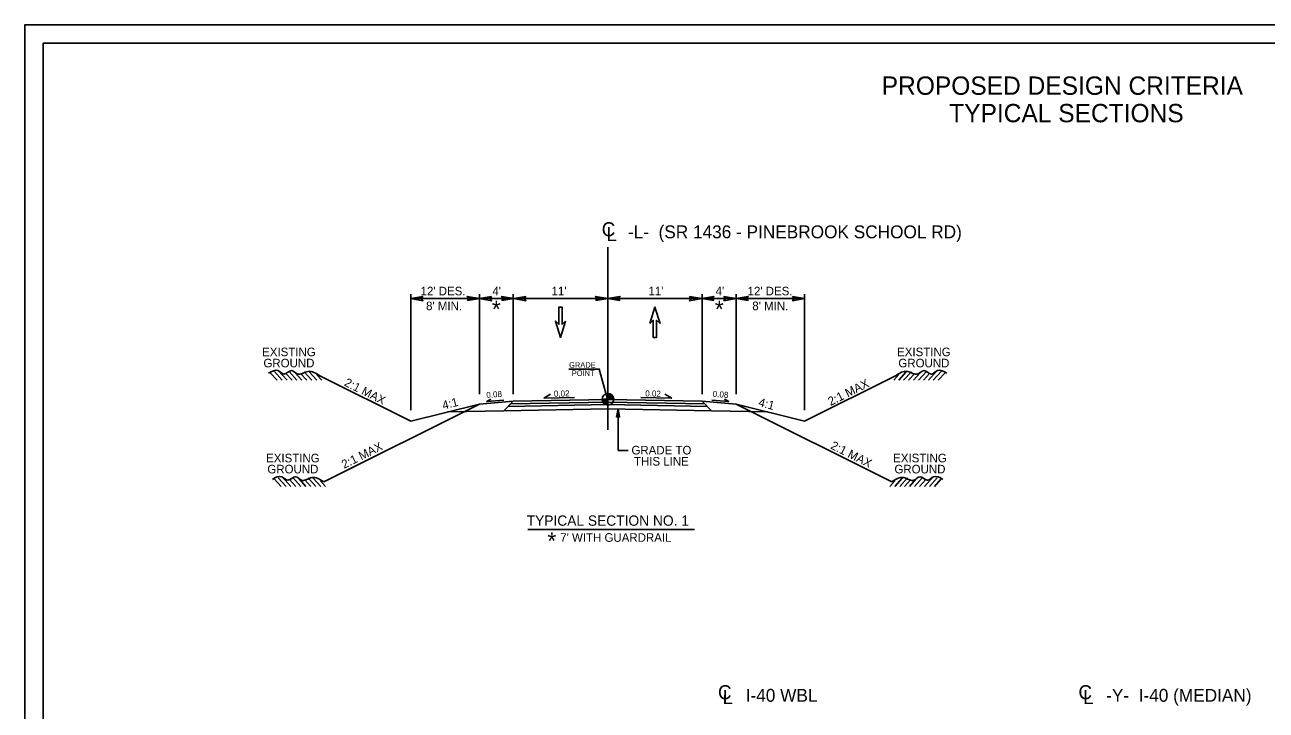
# Model space of a CAD drawing. Extents: x 1553195 to 1553792, y 810516 to 810787.
# Drawn here: x 1553422.4 to 1553567, y 810706.7 to 810786.5 of the extents above; entities that cross this region are included whole.
import ezdxf

# ---------------------------------------------------------------- set-up
doc = ezdxf.new("R2010")
doc.units = 0
for name, color, linetype in [('Old_Level_11', 7, 'Continuous'), ('Prop Dimension', 7, 'Continuous'), ('Prop DSN Text', 7, 'Continuous'), ('Prop Pavement Schedule Description CELL', 7, 'Continuous'), ('Prop Shade Light', 7, 'Continuous'), ('Prop Terminator CELL', 7, 'Continuous'), ('Prop Typical Section', 7, 'Continuous'), ('Sheet Plan CELL', 7, 'Continuous'), ('Typical ID Circle CELL', 7, 'Continuous'), ('Typical Pavement Slope CELL', 7, 'Continuous'), ('Typical Text General CELL', 7, 'Continuous'), ('Typical Text ID Circle CELL', 7, 'Continuous')]:
    doc.layers.add(name, color=color, linetype=linetype)

msp = doc.modelspace()

# ---------------------------------------------------------------- linework, layer by layer
at = {"layer": 'Old_Level_11'}
for p, q in [((1553489.63, 810742.89), (1553490.31, 810742.89)), ((1553490.3, 810742.22), (1553490.31, 810742.89)), ((1553490.31, 810742.89), (1553490.3, 810742.22)), ((1553490.31, 810742.89), (1553490.31, 810743.56)), ((1553490.98, 810742.89), (1553490.31, 810742.89))]:
    msp.add_line(p, q, dxfattribs=at)
for points in [[(1553489.64, 810742.89), (1553489.64, 810742.81)], [(1553489.65, 810742.89), (1553489.65, 810742.74)], [(1553489.66, 810742.89), (1553489.66, 810742.69)], [(1553489.68, 810742.89), (1553489.68, 810742.65)], [(1553489.69, 810742.89), (1553489.69, 810742.62)], [(1553489.7, 810742.89), (1553489.7, 810742.59)], [(1553489.72, 810742.89), (1553489.72, 810742.56)], [(1553489.73, 810742.89), (1553489.73, 810742.54)], [(1553489.75, 810742.89), (1553489.75, 810742.52)], [(1553489.76, 810742.89), (1553489.76, 810742.5)], [(1553489.77, 810742.89), (1553489.77, 810742.48)], [(1553489.79, 810742.89), (1553489.79, 810742.46)], [(1553489.8, 810742.89), (1553489.8, 810742.45)], [(1553489.81, 810742.89), (1553489.81, 810742.43)], [(1553489.83, 810742.89), (1553489.83, 810742.42)], [(1553489.84, 810742.89), (1553489.84, 810742.4)], [(1553489.85, 810742.89), (1553489.85, 810742.39)], [(1553489.87, 810742.89), (1553489.87, 810742.38)], [(1553489.88, 810742.89), (1553489.88, 810742.37)], [(1553489.89, 810742.89), (1553489.89, 810742.36)], [(1553489.91, 810742.89), (1553489.91, 810742.35)], [(1553489.92, 810742.89), (1553489.92, 810742.34)], [(1553489.93, 810742.89), (1553489.93, 810742.33)], [(1553489.95, 810742.89), (1553489.95, 810742.32)], [(1553489.96, 810742.89), (1553489.96, 810742.31)], [(1553489.97, 810742.89), (1553489.97, 810742.3)], [(1553489.99, 810742.89), (1553489.99, 810742.3)], [(1553490, 810742.89), (1553490, 810742.29)], [(1553490.01, 810742.89), (1553490.01, 810742.28)], [(1553490.03, 810742.89), (1553490.03, 810742.28)], [(1553490.04, 810742.89), (1553490.04, 810742.27)], [(1553490.05, 810742.89), (1553490.05, 810742.27)], [(1553490.07, 810742.89), (1553490.07, 810742.26)], [(1553490.08, 810742.89), (1553490.08, 810742.26)], [(1553490.09, 810742.89), (1553490.09, 810742.25)], [(1553490.11, 810742.89), (1553490.11, 810742.25)], [(1553490.12, 810742.89), (1553490.12, 810742.24)], [(1553490.13, 810742.89), (1553490.13, 810742.24)], [(1553490.15, 810742.89), (1553490.15, 810742.24)], [(1553490.16, 810742.89), (1553490.16, 810742.23)], [(1553490.17, 810742.89), (1553490.17, 810742.23)], [(1553490.19, 810742.89), (1553490.19, 810742.23)], [(1553490.2, 810742.89), (1553490.2, 810742.23)], [(1553490.22, 810742.89), (1553490.22, 810742.22)], [(1553490.23, 810742.89), (1553490.23, 810742.22)], [(1553490.24, 810742.89), (1553490.24, 810742.22)], [(1553490.26, 810742.89), (1553490.26, 810742.22)], [(1553490.27, 810742.89), (1553490.27, 810742.22)], [(1553490.28, 810742.89), (1553490.28, 810742.22)], [(1553490.3, 810742.89), (1553490.3, 810742.22), (1553490.3, 810742.22)], [(1553490.31, 810743.56), (1553490.31, 810743.56), (1553490.31, 810742.89)], [(1553490.33, 810743.56), (1553490.33, 810742.89)], [(1553490.34, 810743.56), (1553490.34, 810742.89)], [(1553490.35, 810743.56), (1553490.35, 810742.89)], [(1553490.37, 810743.56), (1553490.37, 810742.89)], [(1553490.38, 810743.55), (1553490.38, 810742.89)], [(1553490.39, 810743.55), (1553490.39, 810742.89)], [(1553490.41, 810743.55), (1553490.41, 810742.89)], [(1553490.42, 810743.55), (1553490.42, 810742.89)], [(1553490.43, 810743.55), (1553490.43, 810742.89)], [(1553490.45, 810743.54), (1553490.45, 810742.89)], [(1553490.46, 810743.54), (1553490.46, 810742.89)], [(1553490.47, 810743.54), (1553490.47, 810742.89)], [(1553490.49, 810743.53), (1553490.49, 810742.89)], [(1553490.5, 810743.53), (1553490.5, 810742.89)], [(1553490.51, 810743.53), (1553490.51, 810742.89)], [(1553490.53, 810743.52), (1553490.53, 810742.89)], [(1553490.54, 810743.52), (1553490.54, 810742.89)], [(1553490.55, 810743.51), (1553490.55, 810742.89)], [(1553490.57, 810743.51), (1553490.57, 810742.89)], [(1553490.58, 810743.5), (1553490.58, 810742.89)], [(1553490.59, 810743.49), (1553490.59, 810742.89)], [(1553490.61, 810743.49), (1553490.61, 810742.89)], [(1553490.62, 810743.48), (1553490.62, 810742.89)], [(1553490.63, 810743.47), (1553490.63, 810742.89)], [(1553490.65, 810743.47), (1553490.65, 810742.89)], [(1553490.66, 810743.46), (1553490.66, 810742.89)], [(1553490.67, 810743.45), (1553490.67, 810742.89)], [(1553490.69, 810743.44), (1553490.69, 810742.89)], [(1553490.7, 810743.43), (1553490.7, 810742.89)], [(1553490.72, 810743.42), (1553490.72, 810742.89)], [(1553490.73, 810743.41), (1553490.73, 810742.89)], [(1553490.74, 810743.4), (1553490.74, 810742.89)], [(1553490.76, 810743.39), (1553490.76, 810742.89)], [(1553490.77, 810743.37), (1553490.77, 810742.89)], [(1553490.78, 810743.36), (1553490.78, 810742.89)], [(1553490.8, 810743.35), (1553490.8, 810742.89)], [(1553490.81, 810743.33), (1553490.81, 810742.89)], [(1553490.82, 810743.32), (1553490.82, 810742.89)], [(1553490.84, 810743.3), (1553490.84, 810742.89)], [(1553490.85, 810743.28), (1553490.85, 810742.89)], [(1553490.86, 810743.26), (1553490.86, 810742.89)], [(1553490.88, 810743.24), (1553490.88, 810742.89)], [(1553490.89, 810743.22), (1553490.89, 810742.89)], [(1553490.9, 810743.2), (1553490.9, 810742.89)], [(1553490.92, 810743.17), (1553490.92, 810742.89)], [(1553490.93, 810743.14), (1553490.93, 810742.89)], [(1553490.94, 810743.1), (1553490.94, 810742.89)], [(1553490.96, 810743.05), (1553490.96, 810742.89)], [(1553490.97, 810742.98), (1553490.97, 810742.89)]]:
    msp.add_lwpolyline(points, dxfattribs=at)
msp.add_circle((1553490.31, 810742.89), 0.671, dxfattribs=at)
for start, end in [(179.9905, 269.9905), (359.9905, 89.9905)]:
    msp.add_arc((1553490.31, 810742.89), 0.671, start, end, dxfattribs=at)
at = {"layer": 'Prop Dimension'}
for p, q in [((1553482.83, 810743.01), (1553483.61, 810743.48)), ((1553482.83, 810743.01), (1553486.43, 810743.08)), ((1553497.74, 810743.01), (1553494.14, 810743.08)), ((1553497.74, 810743.01), (1553496.95, 810743.48))]:
    msp.add_line(p, q, dxfattribs=at)
for points in [[(1553478.16, 810742.79), (1553476.18, 810742.63), (1553476.68, 810742.91)], [(1553502.41, 810742.79), (1553504.38, 810742.63), (1553503.88, 810742.91)]]:
    msp.add_lwpolyline(points, dxfattribs=at)
at = {"layer": 'Prop DSN Text'}
for points in [[(1553468.74, 810754.88), (1553467.33, 810754.63), (1553468.75, 810754.38), (1553468.57, 810754.63)], [(1553473.93, 810754.39), (1553475.33, 810754.63), (1553473.92, 810754.88), (1553474.1, 810754.63)], [(1553476.74, 810754.88), (1553475.33, 810754.63), (1553476.75, 810754.38), (1553476.57, 810754.63)], [(1553477.93, 810754.39), (1553479.33, 810754.63), (1553477.92, 810754.88), (1553478.1, 810754.63)], [(1553480.74, 810754.88), (1553479.33, 810754.63), (1553480.75, 810754.38), (1553480.57, 810754.63)], [(1553488.88, 810754.39), (1553490.28, 810754.63), (1553488.87, 810754.88), (1553489.05, 810754.63)], [(1553491.69, 810754.39), (1553490.28, 810754.63), (1553491.7, 810754.88), (1553491.52, 810754.63)], [(1553499.82, 810754.88), (1553501.23, 810754.63), (1553499.82, 810754.38), (1553500, 810754.63)], [(1553502.64, 810754.39), (1553501.23, 810754.63), (1553502.64, 810754.88), (1553502.46, 810754.63)], [(1553503.82, 810754.88), (1553505.23, 810754.63), (1553503.82, 810754.38), (1553504, 810754.63)], [(1553506.64, 810754.39), (1553505.23, 810754.63), (1553506.64, 810754.88), (1553506.46, 810754.63)], [(1553511.82, 810754.88), (1553513.23, 810754.63), (1553511.82, 810754.38), (1553512, 810754.63)], [(1553491.32, 810740.82), (1553491.49, 810741.76), (1553491.65, 810740.82), (1553491.49, 810740.94)]]:
    msp.add_lwpolyline(points, close=True, dxfattribs=at)
at = {"layer": 'Prop Pavement Schedule Description CELL'}
for p, q in [((1553491.49, 810736.93), (1553491.49, 810741.76)), ((1553492.65, 810736.93), (1553491.49, 810736.93)), ((1553480.98, 810727.73), (1553500.38, 810727.73))]:
    msp.add_line(p, q, dxfattribs=at)
at = {"layer": 'Prop Terminator CELL'}
msp.add_lwpolyline([(1553663.91, 810631.13), (1553663.91, 810784.39), (1553424.51, 810784.39), (1553424.51, 810631.13)], close=True, dxfattribs=at)
at = {"layer": 'Prop Typical Section'}
for p, q in [((1553490.28, 810739.34), (1553490.28, 810760.6)), ((1553467.33, 810741.61), (1553467.33, 810755.13)), ((1553475.33, 810754.63), (1553467.33, 810754.63)), ((1553475.33, 810743.49), (1553475.33, 810755.13)), ((1553479.33, 810754.63), (1553475.33, 810754.63)), ((1553479.28, 810743.49), (1553479.28, 810755.13)), ((1553490.28, 810754.63), (1553479.33, 810754.63)), ((1553490.28, 810754.63), (1553501.23, 810754.63)), ((1553501.23, 810754.63), (1553505.23, 810754.63)), ((1553501.28, 810743.49), (1553501.28, 810755.13)), ((1553505.23, 810743.49), (1553505.23, 810755.13)), ((1553505.23, 810754.63), (1553513.23, 810754.63)), ((1553513.23, 810741.61), (1553513.23, 810755.13))]:
    msp.add_line(p, q, dxfattribs=at)
for points in [[(1553485.38, 810752.01), (1553484.97, 810751.63), (1553484.97, 810753.63), (1553484.59, 810753.63), (1553484.59, 810751.63), (1553484.19, 810752.01), (1553484.78, 810750.1)], [(1553495.19, 810751.73), (1553495.59, 810752.1), (1553495.59, 810750.1), (1553495.97, 810750.1), (1553495.97, 810752.1), (1553496.38, 810751.73), (1553495.78, 810753.63)]]:
    msp.add_lwpolyline(points, close=True, dxfattribs=at)
at = {"layer": 'Sheet Plan CELL'}
msp.add_lwpolyline([(1553666.04, 810628.99), (1553666.04, 810786.53), (1553422.37, 810786.53), (1553422.37, 810628.99)], close=True, dxfattribs=at)
at = {"layer": 'Typical ID Circle CELL'}
for p, q in [((1553456.74, 810745.63), (1553467.33, 810740.33)), ((1553523.82, 810745.63), (1553513.23, 810740.33)), ((1553479.28, 810742.65), (1553475.33, 810742.33)), ((1553501.28, 810742.65), (1553505.23, 810742.33)), ((1553475.33, 810742.33), (1553457.2, 810733.26)), ((1553467.33, 810740.33), (1553475.33, 810742.33)), ((1553478.18, 810741.54), (1553471.65, 810741.41)), ((1553502.39, 810741.54), (1553508.91, 810741.41)), ((1553513.23, 810740.33), (1553505.23, 810742.33)), ((1553505.23, 810742.33), (1553523.37, 810733.26))]:
    msp.add_line(p, q, dxfattribs=at)
at = {"layer": 'Typical Pavement Slope CELL'}
for p, q in [((1553479.28, 810742.65), (1553478.18, 810741.54)), ((1553490.28, 810742.87), (1553479.28, 810742.65)), ((1553490.28, 810742.87), (1553501.28, 810742.65)), ((1553501.28, 810742.65), (1553502.39, 810741.54)), ((1553490.28, 810741.78), (1553478.18, 810741.54)), ((1553490.28, 810742.28), (1553478.69, 810742.05)), ((1553490.28, 810742.57), (1553478.98, 810742.35)), ((1553490.28, 810742.57), (1553501.58, 810742.35)), ((1553490.28, 810742.28), (1553501.88, 810742.05)), ((1553490.28, 810741.78), (1553502.39, 810741.54))]:
    msp.add_line(p, q, dxfattribs=at)
at = {"layer": 'Typical Text General CELL'}
for p, q in [((1553450.97, 810745.98), (1553451.77, 810745.1)), ((1553451.44, 810746.11), (1553452.35, 810745.1)), ((1553451.9, 810746.23), (1553452.92, 810745.1)), ((1553452.79, 810745.89), (1553453.5, 810745.1)), ((1553453.15, 810746.13), (1553454.08, 810745.1)), ((1553453.88, 810745.96), (1553454.65, 810745.1)), ((1553454.5, 810745.91), (1553455.23, 810745.1)), ((1553454.91, 810746.09), (1553455.8, 810745.1)), ((1553455.5, 810746.07), (1553456.38, 810745.1)), ((1553456.35, 810745.77), (1553456.96, 810745.1)), ((1553524.21, 810745.77), (1553523.61, 810745.1)), ((1553525.06, 810746.07), (1553524.19, 810745.1)), ((1553525.66, 810746.09), (1553524.76, 810745.1)), ((1553526.07, 810745.91), (1553525.34, 810745.1)), ((1553526.69, 810745.96), (1553525.91, 810745.1)), ((1553527.41, 810746.13), (1553526.49, 810745.1)), ((1553527.78, 810745.89), (1553527.07, 810745.1)), ((1553528.66, 810746.23), (1553527.64, 810745.1)), ((1553529.13, 810746.11), (1553528.22, 810745.1)), ((1553529.59, 810745.98), (1553528.79, 810745.1)), ((1553451.43, 810733.62), (1553452.23, 810732.73)), ((1553451.89, 810733.75), (1553452.8, 810732.73)), ((1553452.36, 810733.87), (1553453.38, 810732.73)), ((1553453.25, 810733.52), (1553453.96, 810732.73)), ((1553453.61, 810733.76), (1553454.53, 810732.73)), ((1553454.33, 810733.6), (1553455.11, 810732.73)), ((1553454.96, 810733.54), (1553455.68, 810732.73)), ((1553455.37, 810733.73), (1553456.26, 810732.73)), ((1553455.96, 810733.71), (1553456.84, 810732.73)), ((1553456.81, 810733.4), (1553457.41, 810732.73)), ((1553523.75, 810733.4), (1553523.15, 810732.73)), ((1553524.6, 810733.71), (1553523.73, 810732.73)), ((1553525.2, 810733.73), (1553524.3, 810732.73)), ((1553525.61, 810733.54), (1553524.88, 810732.73)), ((1553526.23, 810733.6), (1553525.46, 810732.73)), ((1553526.96, 810733.76), (1553526.03, 810732.73)), ((1553527.32, 810733.52), (1553526.61, 810732.73)), ((1553528.21, 810733.87), (1553527.18, 810732.73)), ((1553528.67, 810733.75), (1553527.76, 810732.73)), ((1553529.13, 810733.62), (1553528.34, 810732.73))]:
    msp.add_line(p, q, dxfattribs=at)
for points in [[(1553456.74, 810745.63), (1553455.35, 810746.13), (1553454.15, 810745.83), (1553453.45, 810746.23), (1553452.56, 810745.83), (1553451.86, 810746.23), (1553450.77, 810745.93)], [(1553523.82, 810745.63), (1553525.22, 810746.13), (1553526.41, 810745.83), (1553527.11, 810746.23), (1553528.01, 810745.83), (1553528.7, 810746.23), (1553529.8, 810745.93)], [(1553457.2, 810733.26), (1553455.8, 810733.76), (1553454.61, 810733.46), (1553453.91, 810733.86), (1553453.02, 810733.46), (1553452.32, 810733.86), (1553451.22, 810733.56)], [(1553523.37, 810733.26), (1553524.76, 810733.76), (1553525.96, 810733.46), (1553526.65, 810733.86), (1553527.55, 810733.46), (1553528.25, 810733.86), (1553529.34, 810733.56)]]:
    msp.add_spline(points, degree=3, dxfattribs=at)
at = {"layer": 'Typical Text ID Circle CELL'}
msp.add_lwpolyline([(1553485.76, 810746.41), (1553489.3, 810746.41), (1553490.27, 810742.89)], dxfattribs=at)

# ---------------------------------------------------------------- texts
at = {"layer": 'Prop Pavement Schedule Description CELL'}
for s, height, p in [('PROPOSED DESIGN CRITERIA', 2.1375, (1553522.21, 810778.37)), ('TYPICAL SECTIONS', 2.1375, (1553530.07, 810775.17)), ('-L-  (SR 1436 - PINEBROOK SCHOOL RD)', 1.5, (1553492.64, 810761.65)), ("12' DES.", 1, (1553468.48, 810755)), ("4'", 1, (1553476.85, 810755)), ("11'", 1, (1553483.74, 810755)), ("11'", 1, (1553495.03, 810755)), ("4'", 1, (1553502.85, 810755)), ("12' DES.", 1, (1553506.58, 810755)), ("8' MIN.", 1, (1553469.12, 810753.27)), ('*', 2, (1553476.78, 810752.39)), ('*', 2, (1553502.76, 810752.39)), ("8' MIN.", 1, (1553507.13, 810753.27)), ('EXISTING', 1, (1553450.02, 810747.91)), ('EXISTING', 1, (1553524, 810747.91)), ('GROUND', 1, (1553450.17, 810746.61)), ('GROUND', 1, (1553524.15, 810746.61)), ('GRADE TO', 1, (1553493.05, 810736.46)), ('EXISTING', 1, (1553450.48, 810735.54)), ('THIS LINE', 1, (1553493.34, 810735.16)), ('EXISTING', 1, (1553523.54, 810735.54)), ('GROUND', 1, (1553450.63, 810734.25)), ('GROUND', 1, (1553523.69, 810734.25)), ('TYPICAL SECTION NO. 1', 1.2, (1553480.84, 810728.15)), ('*', 2, (1553483.25, 810725.38)), ("7' WITH GUARDRAIL", 1, (1553484.75, 810726.28)), ('I-40 WBL', 1.5, (1553506.36, 810707.64)), ('-Y-  I-40 (MEDIAN)', 1.5, (1553548.36, 810707.64))]:
    msp.add_text(s, height=height, dxfattribs=at).set_placement(p)
for s, height, rotation, p in [('2:1 MAX', 1, 333.4349, (1553459.5, 810744.52)), ('2:1 MAX', 1, 26.5651, (1553516.25, 810742.11)), ('4:1', 1, 14.947, (1553471.15, 810741.67)), ('0.08', 0.7, 4.5739, (1553476.17, 810743.03)), ('0.02', 0.7, 1.1459, (1553484.02, 810743.19)), ('0.02', 0.7, 358.8541, (1553494.65, 810743.23)), ('0.08', 0.7, 355.4261, (1553502.5, 810743.18)), ('4:1', 1, 345.053, (1553507.77, 810742.11)), ('2:1 MAX', 1, 26.5651, (1553459.58, 810734.77)), ('2:1 MAX', 1, 333.4349, (1553516.16, 810737.18))]:
    msp.add_text(s, height=height, rotation=rotation, dxfattribs=at).set_placement(p)
at = {"layer": 'Prop Shade Light'}
for p in [(1553489.58, 810761.88), (1553503.13, 810707.93), (1553545.13, 810707.93)]:
    msp.add_text('C', height=1.64, dxfattribs=at).set_placement(p)
for p in [(1553490.13, 810761.32), (1553503.67, 810707.37), (1553545.67, 810707.37)]:
    msp.add_text('L', height=1.64, rotation=359.9469, dxfattribs=at).set_placement(p)
at = {"layer": 'Typical Text ID Circle CELL'}
for s, p in [('GRADE', (1553485.78, 810746.56)), ('POINT', (1553486.09, 810745.6))]:
    msp.add_text(s, height=0.652, dxfattribs=at).set_placement(p)

doc.saveas('drawing.dxf')
